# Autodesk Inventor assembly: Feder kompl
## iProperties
Created: 2006-11
Part Number: Feder kompl
Cost Center: 0,367 kg
Document SubType Name: Assembly
Designer: Schmidt
Authority: 46763 mm^3
Mass: 734.648 g
Surface Area: 588.258 cm^2
Volume: 93.5927 cm^3
Density: 7.84941 g/cm^3
SaveDate: 2006-11-05
SaveTime: 21:24
TotalMass: 0,367 kg
TotalVolume: 46763 mm^3
Author: Schmidt
